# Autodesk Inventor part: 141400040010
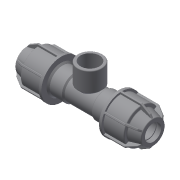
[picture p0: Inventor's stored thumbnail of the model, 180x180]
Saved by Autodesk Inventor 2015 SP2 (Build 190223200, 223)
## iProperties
Created: 2017-08
Part Number: 141400040010
Material: Generic
Description: PLASSON L.14 TEE FEMALE ADAPTOR (SILVER) 40 x 1" x 40
Document SubType Name: Modeling
Designer: KIM
Density: 1 g/cm^3
Appearance: Default
Author: KIM
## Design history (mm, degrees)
derived "141400.ipt"
feature "Solid1::141400.ipt"
feature "Solid2::141400.ipt"
tag "TaggingFeature1"
body "Solid1"
other parameters: "d2" = 62, "d4" = 15 deg, "d5" = 40.92, "d6" = 13.5036, "d10" = 73, "d16" = 40.8, "d17" = 3.1, "d22" = 64, "d24" = 3.1, "d25" = 65.7, "d26" = 54.75, "d27" = 3.1, "d28" = 135 deg, "d29" = 1.86, "d31" = 2, "d46" = 150 deg, "d49" = 3.65, "d50" = 0, "d58" = 1.2, "d61" = 360 deg, "d63" = 36, "d64" = 86.5, "d80" = 57.6, "d81" = 3.2, "d84" = 3.1, "d94" = 63, "d95" = 30.291, "d96" = 39.3783, "d97" = 21, "d98" = 24, "d99" = 31.50264, "d100" = 135 deg, "d108" = 2, "d111" = 0, "G_" = 30.291, "E_" = 73, "H_" = 173, "l_" = 62, "l_2" = 21, "A_" = 63
